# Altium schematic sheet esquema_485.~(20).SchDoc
size A4
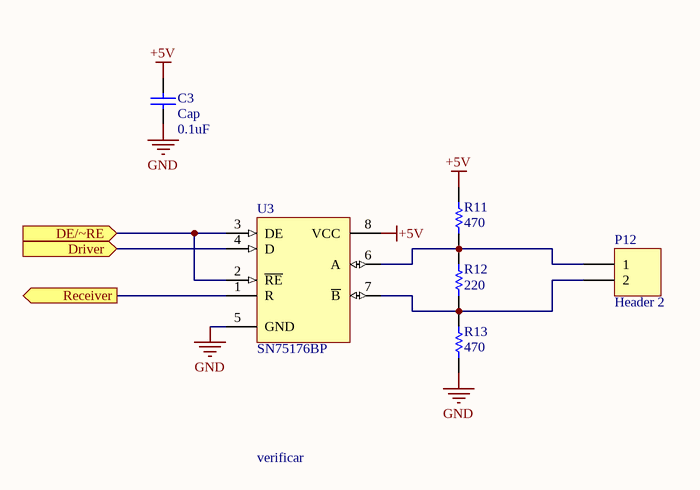
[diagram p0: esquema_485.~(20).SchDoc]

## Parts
C3  Cap  value 0.1uF  [CAPPR2.5-6.3X5]
P12  Header 2  [wf2s]
R11  value 470  [AXIAL-0.3]  (hidden comment: Carbon 1/8w 5%)
R12  value 220  [AXIAL-0.3]  (hidden comment: Carbon 1/8w 5%)
R13  value 470  [AXIAL-0.3]  (hidden comment: Carbon 1/8w 5%)
U3  SN75176BP  [626-05]

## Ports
DE/~RE (in), Driver (in), Receiver (out)

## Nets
+5V: C3.2 R11.2 U3.8(VCC)
GND: C3.1 R13.1 U3.5(GND)
DE/~RE: U3.2(~{RE}) U3.3(DE) ; port DE/~RE
Driver: U3.4(D) ; port Driver
Receiver: U3.1(R) ; port Receiver
NetP12_1: P12.1 R11.1 R12.2 U3.6(A)
NetP12_2: P12.2 R12.1 R13.2 U3.7(~{B})

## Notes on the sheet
- verificar

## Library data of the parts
C3 = Cap: Capacitor
P12 = Header 2: Header, 2-Pin
R11-R13 = Res Semi: Semiconductor Resistor
U3 = SN75176BP: Differential Bus Transceiver; Note: Receiver Hysteresis of 50mV Typical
